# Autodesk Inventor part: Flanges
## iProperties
Created: 2007-02
Part Number: Flanges
Document SubType Name: Sheet Metal
Designer: Admin
Density: 1 g/cm^3
Sheet Metal Rule: Default
Author: Admin
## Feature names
1. Plate1
